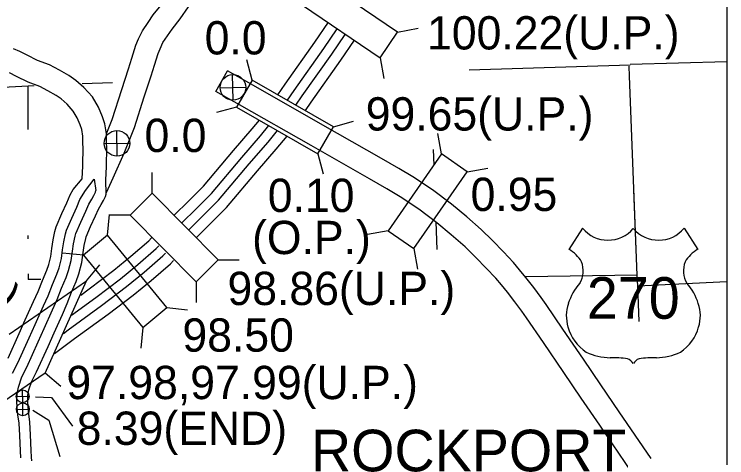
# Model space of a CAD drawing. Extents: x 22866 to 28196, y 1324810 to 1328105.
# Drawn here: x 24428 to 24728.4, y 1327155.3 to 1327342.4 of the extents above; entities that cross this region are included whole.
import ezdxf

# ---------------------------------------------------------------- set-up
doc = ezdxf.new("R2010")
doc.units = 0
for name, color, linetype in [('Level 10', 7, 'Continuous'), ('Level 15', 7, 'Continuous'), ('Level 19', 7, 'Continuous'), ('Level 20', 7, 'Continuous'), ('Level 22', 7, 'Continuous'), ('Level 25', 7, 'Continuous'), ('Level 26', 7, 'Continuous'), ('Level 4', 7, 'Continuous'), ('Level 5', 7, 'Continuous'), ('Level 58', 7, 'Continuous'), ('Level 6', 7, 'Continuous'), ('R_No Plot', 7, 'Continuous')]:
    doc.layers.add(name, color=color, linetype=linetype)

msp = doc.modelspace()

# ---------------------------------------------------------------- linework, layer by layer
at = {"layer": 'Level 10'}
for points in [[(24467.05, 1327292.34), (24469.29, 1327298.02), (24473.35, 1327310.57), (24476.22, 1327319.39), (24477.56, 1327323.87), (24479.26, 1327329.27), (24480.4, 1327331.96), (24482.06, 1327335.4), (24484.45, 1327338.91), (24486.63, 1327342.08), (24489.95, 1327346.26)], [(24467.05, 1327292.34), (24469.29, 1327298.02), (24473.35, 1327310.57), (24476.22, 1327319.39), (24477.56, 1327323.87), (24479.26, 1327329.27), (24480.4, 1327331.96), (24482.06, 1327335.4), (24484.45, 1327338.91), (24486.63, 1327342.08), (24489.95, 1327346.26)], [(24466.86, 1327267.17), (24469.75, 1327273.38), (24474.42, 1327283.83), (24478.69, 1327294.65), (24482.84, 1327307.49), (24485.75, 1327316.42), (24487.09, 1327320.94), (24488.63, 1327325.81), (24489.49, 1327327.84), (24490.72, 1327330.4), (24492.68, 1327333.27), (24494.66, 1327336.14), (24498.03, 1327340.4), (24501.46, 1327345.58)], [(24466.86, 1327267.17), (24469.75, 1327273.38), (24474.42, 1327283.83), (24478.69, 1327294.65), (24482.84, 1327307.49), (24485.75, 1327316.42), (24487.09, 1327320.94), (24488.63, 1327325.81), (24489.49, 1327327.84), (24490.72, 1327330.4), (24492.68, 1327333.27), (24494.66, 1327336.14), (24498.03, 1327340.4), (24501.46, 1327345.58)]]:
    msp.add_lwpolyline(points, dxfattribs=at)
at = {"layer": 'Level 15'}
for points in [[(24466.65, 1327272.59), (24466.87, 1327277.98), (24466.92, 1327280.95), (24467.03, 1327283.49), (24466.99, 1327286.06), (24466.94, 1327288.14), (24466.91, 1327291.88), (24466.16, 1327296.15), (24465.22, 1327299.15), (24463.47, 1327303.19), (24460.96, 1327307.49), (24457.32, 1327311.48), (24453.99, 1327314.46), (24451.07, 1327316.52), (24447.09, 1327318.84), (24442.92, 1327321.05), (24437.84, 1327322.91), (24433.44, 1327325.06), (24430.42, 1327326.6), (24427.67, 1327327.86)], [(24466.65, 1327272.59), (24466.87, 1327277.98), (24466.92, 1327280.95), (24467.03, 1327283.49), (24466.99, 1327286.06), (24466.94, 1327288.14), (24466.91, 1327291.88), (24466.16, 1327296.15), (24465.22, 1327299.15), (24463.47, 1327303.19), (24460.96, 1327307.49), (24457.32, 1327311.48), (24453.99, 1327314.46), (24451.07, 1327316.52), (24447.09, 1327318.84), (24442.92, 1327321.05), (24437.84, 1327322.91), (24433.44, 1327325.06), (24430.42, 1327326.6), (24427.67, 1327327.86)], [(24456.68, 1327273), (24456.9, 1327278.28), (24456.95, 1327281.24), (24457.05, 1327283.63), (24457.02, 1327285.86), (24456.96, 1327287.97), (24456.94, 1327290.97), (24456.44, 1327293.79), (24455.85, 1327295.68), (24454.56, 1327298.68), (24452.88, 1327301.54), (24450.29, 1327304.38), (24447.77, 1327306.64), (24445.68, 1327308.12), (24442.24, 1327310.13), (24438.85, 1327311.92), (24433.93, 1327313.72), (24428.98, 1327316.13), (24426.07, 1327317.63)], [(24456.68, 1327273), (24456.9, 1327278.28), (24456.95, 1327281.24), (24457.05, 1327283.63), (24457.02, 1327285.86), (24456.96, 1327287.97), (24456.94, 1327290.97), (24456.44, 1327293.79), (24455.85, 1327295.68), (24454.56, 1327298.68), (24452.88, 1327301.54), (24450.29, 1327304.38), (24447.77, 1327306.64), (24445.68, 1327308.12), (24442.24, 1327310.13), (24438.85, 1327311.92), (24433.93, 1327313.72), (24428.98, 1327316.13), (24426.07, 1327317.63)], [(24688.33, 1327149.27), (24674.89, 1327169.01), (24667.11, 1327180.41), (24659.75, 1327191.22), (24651.12, 1327203.89), (24644.02, 1327214.25), (24642.07, 1327217.1), (24639.12, 1327221.05), (24635.96, 1327225.11), (24633.43, 1327228.16), (24631.04, 1327230.98), (24627.02, 1327235.31), (24622.68, 1327239.8), (24618.09, 1327244.22), (24612.3, 1327249.39), (24606.23, 1327254.38), (24598.56, 1327260.09), (24590.68, 1327265.36), (24585.15, 1327268.74), (24577.87, 1327272.89), (24553.21, 1327286.96), (24523.02, 1327304.18), (24513.06, 1327309.84), (24517.98, 1327318.51)], [(24688.33, 1327149.27), (24674.89, 1327169.01), (24667.11, 1327180.41), (24659.75, 1327191.22), (24651.12, 1327203.89), (24644.02, 1327214.25), (24642.07, 1327217.1), (24639.12, 1327221.05), (24635.96, 1327225.11), (24633.43, 1327228.16), (24631.04, 1327230.98), (24627.02, 1327235.31), (24622.68, 1327239.8), (24618.09, 1327244.22), (24612.3, 1327249.39), (24606.23, 1327254.38), (24598.56, 1327260.09), (24590.68, 1327265.36), (24585.15, 1327268.74), (24577.87, 1327272.89), (24553.21, 1327286.96), (24523.02, 1327304.18), (24513.06, 1327309.84), (24517.98, 1327318.51)], [(24696.58, 1327154.89), (24683.13, 1327174.62), (24675.35, 1327186.03), (24667.99, 1327196.84), (24659.35, 1327209.52), (24652.25, 1327219.89), (24650.18, 1327222.9), (24647.05, 1327227.1), (24643.74, 1327231.36), (24641.08, 1327234.57), (24638.5, 1327237.6), (24634.26, 1327242.18), (24629.72, 1327246.86), (24624.87, 1327251.54), (24618.79, 1327256.97), (24612.37, 1327262.23), (24604.32, 1327268.24), (24596.05, 1327273.76), (24590.22, 1327277.33), (24582.81, 1327281.55), (24558.15, 1327295.62), (24527.96, 1327312.85), (24517.98, 1327318.51)], [(24696.58, 1327154.89), (24683.13, 1327174.62), (24675.35, 1327186.03), (24667.99, 1327196.84), (24659.35, 1327209.52), (24652.25, 1327219.89), (24650.18, 1327222.9), (24647.05, 1327227.1), (24643.74, 1327231.36), (24641.08, 1327234.57), (24638.5, 1327237.6), (24634.26, 1327242.18), (24629.72, 1327246.86), (24624.87, 1327251.54), (24618.79, 1327256.97), (24612.37, 1327262.23), (24604.32, 1327268.24), (24596.05, 1327273.76), (24590.22, 1327277.33), (24582.81, 1327281.55), (24558.15, 1327295.62), (24527.96, 1327312.85), (24517.98, 1327318.51)], [(24452.92, 1327268.39), (24456.68, 1327273)], [(24452.92, 1327268.39), (24456.68, 1327273)], [(24458, 1327267.97), (24461.66, 1327272.79), (24462.47, 1327267.97)], [(24458, 1327267.97), (24461.66, 1327272.79), (24462.47, 1327267.97)], [(24466.8, 1327266.51), (24466.65, 1327272.59)], [(24466.8, 1327266.51), (24466.65, 1327272.59)], [(24425.42, 1327197.28), (24430.11, 1327207.68), (24432.65, 1327213.42), (24436.19, 1327221.2), (24438.03, 1327225.38), (24439.88, 1327230.12), (24441.72, 1327234.47), (24442.57, 1327236.78), (24443.41, 1327240.14), (24443.89, 1327243.62), (24444.37, 1327247.15), (24445.19, 1327250.77), (24445.67, 1327252.71), (24448.05, 1327258.27), (24450.18, 1327262.79), (24451.62, 1327266.24), (24452.92, 1327268.39)], [(24425.42, 1327197.28), (24430.11, 1327207.68), (24432.65, 1327213.42), (24436.19, 1327221.2), (24438.03, 1327225.38), (24439.88, 1327230.12), (24441.72, 1327234.47), (24442.57, 1327236.78), (24443.41, 1327240.14), (24443.89, 1327243.62), (24444.37, 1327247.15), (24445.19, 1327250.77), (24445.67, 1327252.71), (24448.05, 1327258.27), (24450.18, 1327262.79), (24451.62, 1327266.24), (24452.92, 1327268.39)], [(24427.31, 1327190.97), (24429.54, 1327195.29), (24434.28, 1327205.82), (24436.82, 1327211.55), (24440.36, 1327219.34), (24442.25, 1327223.63), (24444.11, 1327228.4), (24445.98, 1327232.79), (24446.94, 1327235.43), (24447.91, 1327239.27), (24448.42, 1327243), (24448.88, 1327246.33), (24449.64, 1327249.72), (24450.02, 1327251.25), (24452.23, 1327256.39), (24454.36, 1327260.94), (24455.71, 1327264.17), (24458, 1327267.97)], [(24427.31, 1327190.97), (24429.54, 1327195.29), (24434.28, 1327205.82), (24436.82, 1327211.55), (24440.36, 1327219.34), (24442.25, 1327223.63), (24444.11, 1327228.4), (24445.98, 1327232.79), (24446.94, 1327235.43), (24447.91, 1327239.27), (24448.42, 1327243), (24448.88, 1327246.33), (24449.64, 1327249.72), (24450.02, 1327251.25), (24452.23, 1327256.39), (24454.36, 1327260.94), (24455.71, 1327264.17), (24458, 1327267.97)], [(24430.76, 1327155.26), (24430.61, 1327158.16), (24430.34, 1327164.68), (24430.1, 1327169.85), (24429.57, 1327173.32), (24429.29, 1327176.33), (24429.15, 1327179.27), (24429.22, 1327182.17), (24429.75, 1327185.05), (24431.16, 1327189.36), (24433.29, 1327193.48), (24438.08, 1327204.12), (24440.61, 1327209.85), (24444.16, 1327217.64), (24446.09, 1327222.04), (24447.96, 1327226.83), (24449.84, 1327231.26), (24450.92, 1327234.21), (24451.99, 1327238.48), (24452.54, 1327242.44), (24452.97, 1327245.59), (24453.69, 1327248.77), (24453.97, 1327249.93), (24456.02, 1327254.69), (24458.16, 1327259.25), (24459.43, 1327262.28), (24460.67, 1327264.36), (24461.57, 1327265.98), (24462.25, 1327267.32), (24462.47, 1327267.97)], [(24430.76, 1327155.26), (24430.61, 1327158.16), (24430.34, 1327164.68), (24430.1, 1327169.85), (24429.57, 1327173.32), (24429.29, 1327176.33), (24429.15, 1327179.27), (24429.22, 1327182.17), (24429.75, 1327185.05), (24431.16, 1327189.36), (24433.29, 1327193.48), (24438.08, 1327204.12), (24440.61, 1327209.85), (24444.16, 1327217.64), (24446.09, 1327222.04), (24447.96, 1327226.83), (24449.84, 1327231.26), (24450.92, 1327234.21), (24451.99, 1327238.48), (24452.54, 1327242.44), (24452.97, 1327245.59), (24453.69, 1327248.77), (24453.97, 1327249.93), (24456.02, 1327254.69), (24458.16, 1327259.25), (24459.43, 1327262.28), (24460.67, 1327264.36), (24461.57, 1327265.98), (24462.25, 1327267.32), (24462.47, 1327267.97)], [(24435.42, 1327154.04), (24435.32, 1327155.53), (24435.18, 1327158.37), (24434.9, 1327164.89), (24434.65, 1327170.31), (24434.11, 1327173.87), (24433.85, 1327176.65), (24433.72, 1327179.32), (24433.79, 1327181.7), (24434.19, 1327183.93), (24435.39, 1327187.59), (24437.4, 1327191.49), (24442.25, 1327202.26), (24444.78, 1327207.98), (24448.33, 1327215.77), (24450.31, 1327220.29), (24452.19, 1327225.1), (24454.1, 1327229.58), (24455.3, 1327232.86), (24456.49, 1327237.61), (24457.07, 1327241.82), (24457.47, 1327244.78), (24458.14, 1327247.72), (24458.32, 1327248.47), (24460.19, 1327252.82), (24462.34, 1327257.4), (24463.52, 1327260.21), (24464.64, 1327262.07), (24465.61, 1327263.84), (24466.47, 1327265.55), (24466.8, 1327266.51)], [(24435.42, 1327154.04), (24435.32, 1327155.53), (24435.18, 1327158.37), (24434.9, 1327164.89), (24434.65, 1327170.31), (24434.11, 1327173.87), (24433.85, 1327176.65), (24433.72, 1327179.32), (24433.79, 1327181.7), (24434.19, 1327183.93), (24435.39, 1327187.59), (24437.4, 1327191.49), (24442.25, 1327202.26), (24444.78, 1327207.98), (24448.33, 1327215.77), (24450.31, 1327220.29), (24452.19, 1327225.1), (24454.1, 1327229.58), (24455.3, 1327232.86), (24456.49, 1327237.61), (24457.07, 1327241.82), (24457.47, 1327244.78), (24458.14, 1327247.72), (24458.32, 1327248.47), (24460.19, 1327252.82), (24462.34, 1327257.4), (24463.52, 1327260.21), (24464.64, 1327262.07), (24465.61, 1327263.84), (24466.47, 1327265.55), (24466.8, 1327266.51)]]:
    msp.add_lwpolyline(points, dxfattribs=at)
at = {"layer": 'Level 19'}
for points in [[(24539.19, 1327308.4), (24542.24, 1327312.89), (24554.82, 1327330.58), (24560.54, 1327338.98)], [(24539.19, 1327308.4), (24542.24, 1327312.89), (24554.82, 1327330.58), (24560.54, 1327338.98)], [(24543.17, 1327306.11), (24545.99, 1327310.28), (24558.58, 1327327.97), (24564.17, 1327336.19)], [(24543.17, 1327306.11), (24545.99, 1327310.28), (24558.58, 1327327.97), (24564.17, 1327336.19)], [(24546.78, 1327304.03), (24549.41, 1327307.91), (24561.99, 1327325.59), (24567.56, 1327333.79)], [(24546.78, 1327304.03), (24549.41, 1327307.91), (24561.99, 1327325.59), (24567.56, 1327333.79)], [(24550.75, 1327301.75), (24553.16, 1327305.3), (24565.74, 1327322.98), (24571.51, 1327331.46)], [(24550.75, 1327301.75), (24553.16, 1327305.3), (24565.74, 1327322.98), (24571.51, 1327331.46)], [(24495.36, 1327257.49), (24501.56, 1327263.65), (24507.76, 1327269.87), (24520.49, 1327284.96), (24528.35, 1327293.99), (24531.38, 1327297.7)], [(24495.36, 1327257.49), (24501.56, 1327263.65), (24507.76, 1327269.87), (24520.49, 1327284.96), (24528.35, 1327293.99), (24531.38, 1327297.7)], [(24498.6, 1327254.26), (24504.79, 1327260.41), (24511.13, 1327266.78), (24523.96, 1327281.99), (24531.85, 1327291.04), (24535.4, 1327295.39)], [(24498.6, 1327254.26), (24504.79, 1327260.41), (24511.13, 1327266.78), (24523.96, 1327281.99), (24531.85, 1327291.04), (24535.4, 1327295.39)], [(24501.54, 1327251.32), (24507.73, 1327257.47), (24514.2, 1327263.97), (24527.12, 1327279.28), (24535.03, 1327288.36), (24539.05, 1327293.29)], [(24501.54, 1327251.32), (24507.73, 1327257.47), (24514.2, 1327263.97), (24527.12, 1327279.28), (24535.03, 1327288.36), (24539.05, 1327293.29)], [(24504.77, 1327248.09), (24510.96, 1327254.24), (24517.57, 1327260.87), (24530.59, 1327276.3), (24538.52, 1327285.41), (24543.07, 1327290.98)], [(24504.77, 1327248.09), (24510.96, 1327254.24), (24517.57, 1327260.87), (24530.59, 1327276.3), (24538.52, 1327285.41), (24543.07, 1327290.98)], [(24456.03, 1327223.87), (24459.65, 1327226.51), (24469.98, 1327234.37), (24477.2, 1327240.29), (24484.75, 1327246.83), (24485.91, 1327248)], [(24456.03, 1327223.87), (24459.65, 1327226.51), (24469.98, 1327234.37), (24477.2, 1327240.29), (24484.75, 1327246.83), (24485.91, 1327248)], [(24452.13, 1327215.38), (24462.38, 1327222.85), (24472.81, 1327230.78), (24480.14, 1327236.8), (24487.88, 1327243.49), (24488.99, 1327244.62)], [(24452.13, 1327215.38), (24462.38, 1327222.85), (24472.81, 1327230.78), (24480.14, 1327236.8), (24487.88, 1327243.49), (24488.99, 1327244.62)], [(24448.72, 1327207.74), (24450.77, 1327209.24), (24464.86, 1327219.51), (24475.39, 1327227.52), (24482.82, 1327233.62), (24490.73, 1327240.46), (24491.83, 1327241.57)], [(24448.72, 1327207.74), (24450.77, 1327209.24), (24464.86, 1327219.51), (24475.39, 1327227.52), (24482.82, 1327233.62), (24490.73, 1327240.46), (24491.83, 1327241.57)], [(24444.92, 1327199.29), (24453.46, 1327205.55), (24467.59, 1327215.85), (24478.22, 1327223.93), (24485.77, 1327230.12), (24493.86, 1327237.12), (24495.16, 1327238.44)], [(24444.92, 1327199.29), (24453.46, 1327205.55), (24467.59, 1327215.85), (24478.22, 1327223.93), (24485.77, 1327230.12), (24493.86, 1327237.12), (24495.16, 1327238.44)]]:
    msp.add_lwpolyline(points, dxfattribs=at)
at = {"layer": 'Level 20'}
for p, q in [((24589.66, 1327334.85), (24598.28, 1327336.49)), ((24589.66, 1327334.85), (24598.28, 1327336.49)), ((24528.33, 1327314.64), (24526.05, 1327323.12)), ((24528.33, 1327314.64), (24526.05, 1327323.12)), ((24582.25, 1327323.96), (24583.89, 1327315.34)), ((24582.25, 1327323.96), (24583.89, 1327315.34)), ((24521.77, 1327303.23), (24513.29, 1327300.95)), ((24521.77, 1327303.23), (24513.29, 1327300.95)), ((24562.57, 1327294.95), (24571.05, 1327297.23)), ((24562.57, 1327294.95), (24571.05, 1327297.23)), ((24608.23, 1327283.46), (24606.68, 1327292.1)), ((24608.23, 1327283.46), (24606.68, 1327292.1)), ((24556.01, 1327283.53), (24558.29, 1327275.06)), ((24556.01, 1327283.53), (24558.29, 1327275.06)), ((24619.03, 1327275.93), (24627.67, 1327277.48)), ((24619.03, 1327275.93), (24627.67, 1327277.48)), ((24486.19, 1327266.85), (24486.22, 1327275.62)), ((24486.19, 1327266.85), (24486.22, 1327275.62)), ((24467.32, 1327249.14), (24468.18, 1327257.87)), ((24467.32, 1327249.14), (24468.18, 1327257.87)), ((24476.85, 1327257.57), (24468.07, 1327257.6)), ((24476.85, 1327257.57), (24468.07, 1327257.6)), ((24585.64, 1327251.06), (24577, 1327249.51)), ((24585.64, 1327251.06), (24577, 1327249.51)), ((24457.15, 1327240.78), (24448.41, 1327241.64)), ((24457.15, 1327240.78), (24448.41, 1327241.64)), ((24596.44, 1327243.53), (24597.99, 1327234.89)), ((24596.44, 1327243.53), (24597.99, 1327234.89)), ((24514.03, 1327238.82), (24522.8, 1327238.79)), ((24514.03, 1327238.82), (24522.8, 1327238.79)), ((24458.54, 1327229.95), (24464.16, 1327236.69)), ((24458.54, 1327229.95), (24464.16, 1327236.69)), ((24425.91, 1327207.41), (24458.54, 1327229.95)), ((24425.91, 1327207.41), (24458.54, 1327229.95)), ((24440.98, 1327190.96), (24458.54, 1327229.95)), ((24440.98, 1327190.96), (24458.54, 1327229.95)), ((24504.69, 1327229.54), (24504.66, 1327220.77)), ((24504.69, 1327229.54), (24504.66, 1327220.77)), ((24492.38, 1327218.6), (24501.12, 1327217.74)), ((24492.38, 1327218.6), (24501.12, 1327217.74)), ((24482.21, 1327210.25), (24481.35, 1327201.52)), ((24482.21, 1327210.25), (24481.35, 1327201.52)), ((24440.98, 1327190.96), (24408.4, 1327168.52)), ((24440.98, 1327190.96), (24408.4, 1327168.52)), ((24447.72, 1327185.34), (24440.98, 1327190.96)), ((24447.72, 1327185.34), (24440.98, 1327190.96))]:
    msp.add_line(p, q, dxfattribs=at)
for points in [[(24549.59, 1327346.18), (24582.25, 1327323.96), (24589.66, 1327334.85), (24557, 1327357.06)], [(24549.59, 1327346.18), (24582.25, 1327323.96), (24589.66, 1327334.85), (24557, 1327357.06)], [(24521.77, 1327303.23), (24556.01, 1327283.53), (24562.57, 1327294.95), (24528.33, 1327314.64)], [(24521.77, 1327303.23), (24556.01, 1327283.53), (24562.57, 1327294.95), (24528.33, 1327314.64)], [(24596.44, 1327243.53), (24619.03, 1327275.93), (24608.23, 1327283.46), (24585.64, 1327251.06)], [(24596.44, 1327243.53), (24619.03, 1327275.93), (24608.23, 1327283.46), (24585.64, 1327251.06)], [(24514.03, 1327238.82), (24486.19, 1327266.85), (24476.85, 1327257.57), (24504.69, 1327229.54)], [(24514.03, 1327238.82), (24486.19, 1327266.85), (24476.85, 1327257.57), (24504.69, 1327229.54)], [(24457.15, 1327240.78), (24482.21, 1327210.25), (24492.38, 1327218.6), (24467.32, 1327249.14)], [(24457.15, 1327240.78), (24482.21, 1327210.25), (24492.38, 1327218.6), (24467.32, 1327249.14)]]:
    msp.add_lwpolyline(points, close=True, dxfattribs=at)
at = {"layer": 'Level 22'}
for p, q in [((24667.66, 1327252.08), (24661.9, 1327243.18)), ((24667.66, 1327252.08), (24661.9, 1327243.18)), ((24710.44, 1327252.08), (24716.2, 1327243.18)), ((24710.44, 1327252.08), (24716.2, 1327243.18))]:
    msp.add_line(p, q, dxfattribs=at)
for centre, radius, start, end in [((24678.37, 1327261.09), 14.01, 220.075, 319.6701), ((24678.37, 1327261.09), 14.01, 220.075, 319.6701), ((24699.73, 1327261.09), 14.01, 220.3299, 319.925), ((24699.73, 1327261.09), 14.01, 220.3299, 319.925), ((24654.38, 1327230.26), 14.95, 30.7809, 59.9883), ((24654.38, 1327230.26), 14.95, 30.7809, 59.9883), ((24723.72, 1327230.26), 14.95, 120.0117, 149.2191), ((24723.72, 1327230.26), 14.95, 120.0117, 149.2191), ((24657.67, 1327234.2), 10.25, 328.8105, 21.2108), ((24657.67, 1327234.2), 10.25, 328.8105, 21.2108), ((24720.43, 1327234.2), 10.25, 158.7892, 211.1895), ((24720.43, 1327234.2), 10.25, 158.7892, 211.1895), ((24684.47, 1327213.19), 23.91, 138.9565, 162.6913), ((24684.47, 1327213.19), 23.91, 138.9565, 162.6913), ((24693.63, 1327213.19), 23.91, 17.3087, 41.0435), ((24693.63, 1327213.19), 23.91, 17.3087, 41.0435), ((24676.58, 1327215.15), 15.8, 160.9576, 197.3819), ((24676.58, 1327215.15), 15.8, 160.9576, 197.3819), ((24701.52, 1327215.15), 15.8, 342.6181, 19.0424), ((24701.52, 1327215.15), 15.8, 342.6181, 19.0424), ((24679.15, 1327215.2), 18.28, 195.1074, 237.1312), ((24679.15, 1327215.2), 18.28, 195.1074, 237.1312), ((24698.95, 1327215.2), 18.28, 302.8688, 344.8926), ((24698.95, 1327215.2), 18.28, 302.8688, 344.8926), ((24679.49, 1327220.96), 23.48, 244.0771, 269.5779), ((24679.49, 1327220.96), 23.48, 244.0771, 269.5779), ((24698.61, 1327220.96), 23.48, 270.4221, 295.9229), ((24698.61, 1327220.96), 23.48, 270.4221, 295.9229), ((24680.04, 1327154.49), 43, 81.1942, 90.9539), ((24680.04, 1327154.49), 43, 81.1942, 90.9539), ((24685.41, 1327193.04), 4.12, 28.0342, 72.9864), ((24685.41, 1327193.04), 4.12, 28.0342, 72.9864), ((24692.69, 1327193.04), 4.12, 107.0136, 151.9658), ((24692.69, 1327193.04), 4.12, 107.0136, 151.9658), ((24698.07, 1327154.49), 43, 89.0461, 98.8058), ((24698.07, 1327154.49), 43, 89.0461, 98.8058)]:
    msp.add_arc(centre, radius, start, end, dxfattribs=at)
at = {"layer": 'Level 25'}
for points in [[(24436.96, 1327181.04), (24443.71, 1327180.69), (24452.58, 1327168.61)], [(24436.96, 1327181.04), (24443.71, 1327180.69), (24452.58, 1327168.61)], [(24435.9, 1327175.36), (24442.64, 1327171.1), (24447.26, 1327155.82)], [(24435.9, 1327175.36), (24442.64, 1327171.1), (24447.26, 1327155.82)]]:
    msp.add_lwpolyline(points, dxfattribs=at)
at = {"layer": 'Level 26'}
for p, q in [((24520.34, 1327306.1), (24520.09, 1327316.92)), ((24520.34, 1327306.1), (24520.09, 1327316.92)), ((24514.8, 1327311.38), (24525.62, 1327311.63)), ((24514.8, 1327311.38), (24525.62, 1327311.63)), ((24471.45, 1327282.51), (24471.2, 1327293.34)), ((24471.45, 1327282.51), (24471.2, 1327293.34)), ((24465.91, 1327287.8), (24476.74, 1327288.05)), ((24465.91, 1327287.8), (24476.74, 1327288.05)), ((24428.83, 1327181.1), (24434.24, 1327181.22)), ((24428.83, 1327181.1), (24434.24, 1327181.22)), ((24431.59, 1327178.45), (24431.47, 1327183.86)), ((24431.59, 1327178.45), (24431.47, 1327183.86)), ((24431.7, 1327173), (24431.58, 1327178.42)), ((24431.7, 1327173), (24431.58, 1327178.42)), ((24428.93, 1327175.65), (24434.34, 1327175.77)), ((24428.93, 1327175.65), (24434.34, 1327175.77))]:
    msp.add_line(p, q, dxfattribs=at)
for centre, radius in [((24520.21, 1327311.51), 5.41), ((24520.21, 1327311.51), 5.41), ((24471.32, 1327287.92), 5.41), ((24471.32, 1327287.92), 5.41), ((24431.53, 1327181.16), 2.71), ((24431.53, 1327181.16), 2.71), ((24431.64, 1327175.71), 2.71), ((24431.64, 1327175.71), 2.71)]:
    msp.add_circle(centre, radius, dxfattribs=at)
at = {"layer": 'Level 4'}
for points in [[(24728.44, 1327322.27), (24687.7, 1327321.23)], [(24728.44, 1327322.27), (24687.7, 1327321.23)], [(24687.71, 1327320.96), (24619.89, 1327318.78)], [(24687.71, 1327320.96), (24619.89, 1327318.78)], [(24687.41, 1327316.22), (24687.23, 1327320.48)], [(24687.41, 1327316.22), (24687.23, 1327320.48)], [(24691.49, 1327212.7), (24690.96, 1327227.62), (24690.72, 1327232.31), (24687.41, 1327316.22)], [(24469.48, 1327313.5), (24456.59, 1327312.97)], [(24469.48, 1327313.5), (24456.59, 1327312.97)], [(24436.45, 1327312.14), (24433.83, 1327312.04), (24425.83, 1327311.63), (24341.78, 1327307.69), (24333.92, 1327307.41), (24305.09, 1327305.86)], [(24436.45, 1327312.14), (24433.83, 1327312.04), (24425.83, 1327311.63), (24341.78, 1327307.69), (24333.92, 1327307.41), (24305.09, 1327305.86)], [(24691.49, 1327212.7), (24690.96, 1327227.62), (24690.72, 1327232.31), (24689.3, 1327268.26)]]:
    msp.add_lwpolyline(points, dxfattribs=at)
at = {"layer": 'Level 5'}
for points in [[(24433.85, 1327293.81), (24433.83, 1327312.04)], [(24433.85, 1327293.81), (24433.83, 1327312.04)], [(24604.68, 1327285.38), (24604.92, 1327278.71)], [(24604.68, 1327285.38), (24604.92, 1327278.71)], [(24605.77, 1327254.87), (24606.19, 1327243.08)], [(24605.77, 1327254.87), (24606.19, 1327243.08)], [(24433.91, 1327247.68), (24433.91, 1327248.97)], [(24433.91, 1327247.68), (24433.91, 1327248.97)], [(24433.9, 1327232.93), (24433.86, 1327230.53)], [(24433.9, 1327232.93), (24433.86, 1327230.53)], [(24690.72, 1327232.31), (24643.65, 1327231.65)], [(24690.72, 1327232.31), (24643.65, 1327231.65)], [(24439.28, 1327230.41), (24433.86, 1327230.53)], [(24439.28, 1327230.41), (24433.86, 1327230.53)], [(24728.44, 1327229.51), (24690.96, 1327227.62)], [(24728.44, 1327229.51), (24690.96, 1327227.62)]]:
    msp.add_lwpolyline(points, dxfattribs=at)
at = {"layer": 'R_No Plot'}
msp.add_lwpolyline([(23932.69, 1327446.26), (24728.44, 1327446.26), (24728.44, 1326652.92), (23932.69, 1326652.92)], close=True, dxfattribs=at)

# ---------------------------------------------------------------- texts
at = {"layer": 'Level 22'}
msp.add_text('270', height=17.555, dxfattribs=at).set_placement((24669.44, 1327213.91))
msp.add_text('270', height=17.555, dxfattribs=at).set_placement((24669.44, 1327213.91))
at = {"layer": 'Level 25'}
for s, p in [('0.0', (24508.3, 1327325.43)), ('0.0', (24508.3, 1327325.43)), ('0.0', (24482.95, 1327284.26)), ('0.0', (24482.95, 1327284.26)), ('8.39(END)', (24454.34, 1327160.71)), ('8.39(END)', (24454.34, 1327160.71))]:
    msp.add_text(s, height=14.044, dxfattribs=at).set_placement(p)
at = {"layer": 'Level 58'}
for s, height, p in [('100.22(U.P.)', 14.0442, (24602.08, 1327327.52)), ('100.22(U.P.)', 14.0442, (24602.08, 1327327.52)), ('99.65(U.P.)', 14.0442, (24576.21, 1327293.32)), ('99.65(U.P.)', 14.0442, (24576.21, 1327293.32)), ('0.10', 14.044, (24534.91, 1327258.96)), ('0.10', 14.044, (24534.91, 1327258.96)), ('0.95', 14.044, (24620.44, 1327259.39)), ('0.95', 14.044, (24620.44, 1327259.39)), ('(O.P.)', 14.044, (24528.29, 1327241.19)), ('(O.P.)', 14.044, (24528.29, 1327241.19)), ('98.86(U.P.)', 14.0442, (24517.92, 1327219.7)), ('98.86(U.P.)', 14.0442, (24517.92, 1327219.7)), ('98.50', 14.044, (24498.92, 1327200.03)), ('98.50', 14.044, (24498.92, 1327200.03)), ('97.98,97.99(U.P.)', 14.0442, (24449.99, 1327180.01)), ('97.98,97.99(U.P.)', 14.0442, (24449.99, 1327180.01))]:
    msp.add_text(s, height=height, dxfattribs=at).set_placement(p)
msp.add_text('8.20(O.P.)', height=14.044, rotation=310, dxfattribs=at).set_placement((24365.41, 1327281.82))
msp.add_text('8.20(O.P.)', height=14.044, rotation=310, dxfattribs=at).set_placement((24365.41, 1327281.82))
at = {"layer": 'Level 6'}
msp.add_text('ROCKPORT', height=17.555, dxfattribs=at).set_placement((24553.11, 1327149.54))
msp.add_text('ROCKPORT', height=17.555, dxfattribs=at).set_placement((24553.11, 1327149.54))

doc.saveas('drawing.dxf')
